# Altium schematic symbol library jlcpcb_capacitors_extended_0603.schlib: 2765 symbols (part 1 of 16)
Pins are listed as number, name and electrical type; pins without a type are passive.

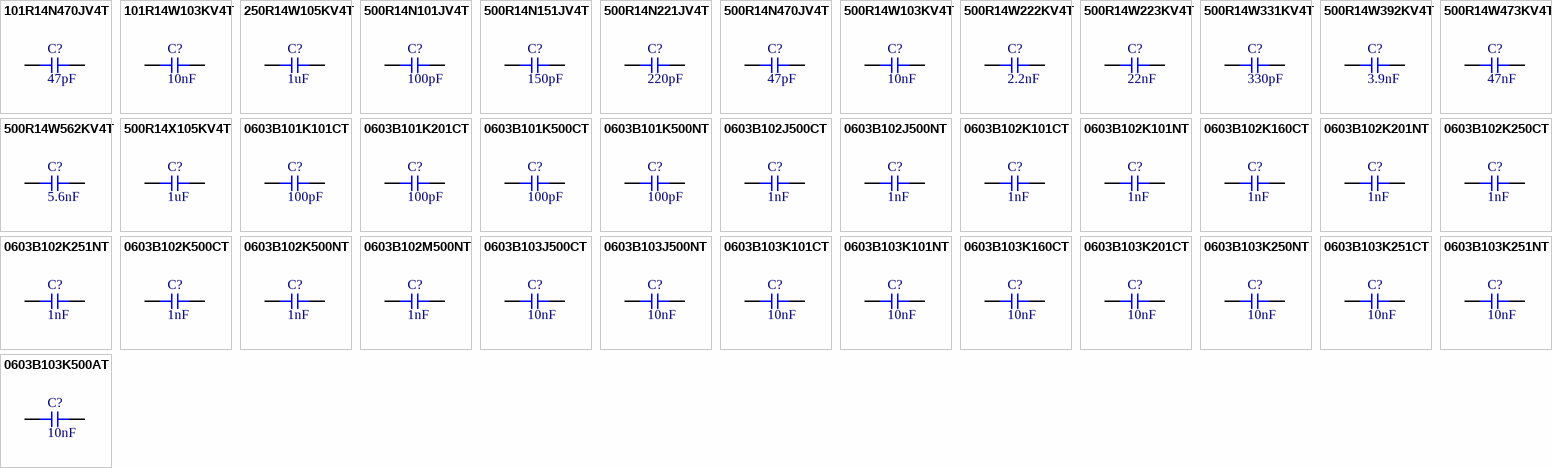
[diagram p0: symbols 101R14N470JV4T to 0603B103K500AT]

## 101R14N470JV4T
designator C?  Capacitance: 47pF  (hidden comment: *)
Capacitor, Ceramic (MLCC), 47pF, ±5%, 100V, NP0, ±5%, SMD 0603; Manufacturer: Johanson Dielectrics; Manufacturer Part Number: 101R14N470JV4T
footprint CAP-0603 (0603 (1608M) Capacitor)
pins: 1, 2

## 101R14W103KV4T
designator C?  Capacitance: 10nF  (hidden comment: *)
Capacitor, Ceramic (MLCC), 10nF, ±10%, 100V, X7R, ±10%, SMD 0603; Manufacturer: Johanson Dielectrics; Manufacturer Part Number: 101R14W103KV4T
footprint CAP-0603 (0603 (1608M) Capacitor)
pins: 1, 2

## 250R14W105KV4T
designator C?  Capacitance: 1uF  (hidden comment: *)
Capacitor, Ceramic (MLCC), 1uF, ±10%, 25V, X7R, ±10%, SMD 0603; Manufacturer: Johanson Dielectrics; Manufacturer Part Number: 250R14W105KV4T
footprint CAP-0603 (0603 (1608M) Capacitor)
pins: 1, 2

## 500R14N101JV4T
designator C?  Capacitance: 100pF  (hidden comment: *)
Capacitor, Ceramic (MLCC), 100pF, ±5%, 50V, NP0, ±5%, SMD 0603; Manufacturer: Johanson Dielectrics; Manufacturer Part Number: 500R14N101JV4T
footprint CAP-0603 (0603 (1608M) Capacitor)
pins: 1, 2

## 500R14N151JV4T
designator C?  Capacitance: 150pF  (hidden comment: *)
Capacitor, Ceramic (MLCC), 150pF, ±5%, 50V, NP0, ±5%, SMD 0603; Manufacturer: Johanson Dielectrics; Manufacturer Part Number: 500R14N151JV4T
footprint CAP-0603 (0603 (1608M) Capacitor)
pins: 1, 2

## 500R14N221JV4T
designator C?  Capacitance: 220pF  (hidden comment: *)
Capacitor, Ceramic (MLCC), 220pF, ±5%, 50V, NP0, ±5%, SMD 0603; Manufacturer: Johanson Dielectrics; Manufacturer Part Number: 500R14N221JV4T
footprint CAP-0603 (0603 (1608M) Capacitor)
pins: 1, 2

## 500R14N470JV4T
designator C?  Capacitance: 47pF  (hidden comment: *)
Capacitor, Ceramic (MLCC), 47pF, ±5%, 50V, NP0, ±5%, SMD 0603; Manufacturer: Johanson Dielectrics; Manufacturer Part Number: 500R14N470JV4T
footprint CAP-0603 (0603 (1608M) Capacitor)
pins: 1, 2

## 500R14W103KV4T
designator C?  Capacitance: 10nF  (hidden comment: *)
Capacitor, Ceramic (MLCC), 10nF, ±10%, 50V, X7R, ±10%, SMD 0603; Manufacturer: Johanson Dielectrics; Manufacturer Part Number: 500R14W103KV4T
footprint CAP-0603 (0603 (1608M) Capacitor)
pins: 1, 2

## 500R14W222KV4T
designator C?  Capacitance: 2.2nF  (hidden comment: *)
Capacitor, Ceramic (MLCC), 2.2nF, ±10%, 50V, X7R, ±10%, SMD 0603; Manufacturer: Johanson Dielectrics; Manufacturer Part Number: 500R14W222KV4T
footprint CAP-0603 (0603 (1608M) Capacitor)
pins: 1, 2

## 500R14W223KV4T
designator C?  Capacitance: 22nF  (hidden comment: *)
Capacitor, Ceramic (MLCC), 22nF, ±10%, 50V, X7R, ±10%, SMD 0603; Manufacturer: Johanson Dielectrics; Manufacturer Part Number: 500R14W223KV4T
footprint CAP-0603 (0603 (1608M) Capacitor)
pins: 1, 2

## 500R14W331KV4T
designator C?  Capacitance: 330pF  (hidden comment: *)
Capacitor, Ceramic (MLCC), 330pF, ±10%, 50V, X7R, ±10%, SMD 0603; Manufacturer: Johanson Dielectrics; Manufacturer Part Number: 500R14W331KV4T
footprint CAP-0603 (0603 (1608M) Capacitor)
pins: 1, 2

## 500R14W392KV4T
designator C?  Capacitance: 3.9nF  (hidden comment: *)
Capacitor, Ceramic (MLCC), 3.9nF, ±10%, 50V, X7R, ±10%, SMD 0603; Manufacturer: Johanson Dielectrics; Manufacturer Part Number: 500R14W392KV4T
footprint CAP-0603 (0603 (1608M) Capacitor)
pins: 1, 2

## 500R14W473KV4T
designator C?  Capacitance: 47nF  (hidden comment: *)
Capacitor, Ceramic (MLCC), 47nF, ±10%, 50V, X7R, ±10%, SMD 0603; Manufacturer: Johanson Dielectrics; Manufacturer Part Number: 500R14W473KV4T
footprint CAP-0603 (0603 (1608M) Capacitor)
pins: 1, 2

## 500R14W562KV4T
designator C?  Capacitance: 5.6nF  (hidden comment: *)
Capacitor, Ceramic (MLCC), 5.6nF, ±10%, 50V, X7R, ±10%, SMD 0603; Manufacturer: Johanson Dielectrics; Manufacturer Part Number: 500R14W562KV4T
footprint CAP-0603 (0603 (1608M) Capacitor)
pins: 1, 2

## 500R14X105KV4T
designator C?  Capacitance: 1uF  (hidden comment: *)
Capacitor, Ceramic (MLCC), 1uF, ±10%, 50V, X5R, ±10%, SMD 0603; Manufacturer: Johanson Dielectrics; Manufacturer Part Number: 500R14X105KV4T
footprint CAP-0603 (0603 (1608M) Capacitor)
pins: 1, 2

## 0603B101K101CT
designator C?  Capacitance: 100pF  (hidden comment: *)
Capacitor, Ceramic (MLCC), 100pF, ±10%, 100V, X7R, ±10%, SMD 0603; Manufacturer: Walsin Tech Corp; Manufacturer Part Number: 0603B101K101CT
footprint CAP-0603 (0603 (1608M) Capacitor)
pins: 1, 2

## 0603B101K201CT
designator C?  Capacitance: 100pF  (hidden comment: *)
Capacitor, Ceramic (MLCC), 100pF, ±10%, 200V, X7R, ±10%, SMD 0603; Manufacturer: Walsin Tech Corp; Manufacturer Part Number: 0603B101K201CT
footprint CAP-0603 (0603 (1608M) Capacitor)
pins: 1, 2

## 0603B101K500CT
designator C?  Capacitance: 100pF  (hidden comment: *)
Capacitor, Ceramic (MLCC), 100pF, ±10%, 50V, X7R, ±10%, SMD 0603; Manufacturer: Walsin Tech Corp; Manufacturer Part Number: 0603B101K500CT
footprint CAP-0603 (0603 (1608M) Capacitor)
pins: 1, 2

## 0603B101K500NT
designator C?  Capacitance: 100pF  (hidden comment: *)
Capacitor, Ceramic (MLCC), 100pF, ±10%, 50V, X7R, ±10%, SMD 0603; Manufacturer: FH(Guangdong Fenghua Advanced Tech); Manufacturer Part Number: 0603B101K500NT
footprint CAP-0603 (0603 (1608M) Capacitor)
pins: 1, 2

## 0603B102J500CT
designator C?  Capacitance: 1nF  (hidden comment: *)
Capacitor, Ceramic (MLCC), 1nF, ±5%, 50V, X7R, ±5%, SMD 0603; Manufacturer: Walsin Tech Corp; Manufacturer Part Number: 0603B102J500CT
footprint CAP-0603 (0603 (1608M) Capacitor)
pins: 1, 2

## 0603B102J500NT
designator C?  Capacitance: 1nF  (hidden comment: *)
Capacitor, Ceramic (MLCC), 1nF, ±5%, 50V, X7R, ±5%, SMD 0603; Manufacturer: FH(Guangdong Fenghua Advanced Tech); Manufacturer Part Number: 0603B102J500NT
footprint CAP-0603 (0603 (1608M) Capacitor)
pins: 1, 2

## 0603B102K101CT
designator C?  Capacitance: 1nF  (hidden comment: *)
Capacitor, Ceramic (MLCC), 1nF, ±10%, 100V, X7R, ±10%, SMD 0603; Manufacturer: Walsin Tech Corp; Manufacturer Part Number: 0603B102K101CT
footprint CAP-0603 (0603 (1608M) Capacitor)
pins: 1, 2

## 0603B102K101NT
designator C?  Capacitance: 1nF  (hidden comment: *)
Capacitor, Ceramic (MLCC), 1nF, ±10%, 100V, X7R, ±10%, SMD 0603; Manufacturer: FH(Guangdong Fenghua Advanced Tech); Manufacturer Part Number: 0603B102K101NT
footprint CAP-0603 (0603 (1608M) Capacitor)
pins: 1, 2

## 0603B102K160CT
designator C?  Capacitance: 1nF  (hidden comment: *)
Capacitor, Ceramic (MLCC), 1nF, ±10%, 16V, X7R, ±10%, SMD 0603; Manufacturer: Walsin Tech Corp; Manufacturer Part Number: 0603B102K160CT
footprint CAP-0603 (0603 (1608M) Capacitor)
pins: 1, 2

## 0603B102K201NT
designator C?  Capacitance: 1nF  (hidden comment: *)
Capacitor, Ceramic (MLCC), 1nF, ±10%, 200V, X7R, ±10%, SMD 0603; Manufacturer: FH(Guangdong Fenghua Advanced Tech); Manufacturer Part Number: 0603B102K201NT
footprint CAP-0603 (0603 (1608M) Capacitor)
pins: 1, 2

## 0603B102K250CT
designator C?  Capacitance: 1nF  (hidden comment: *)
Capacitor, Ceramic (MLCC), 1nF, ±10%, 25V, X7R, ±10%, SMD 0603; Manufacturer: Walsin Tech Corp; Manufacturer Part Number: 0603B102K250CT
footprint CAP-0603 (0603 (1608M) Capacitor)
pins: 1, 2

## 0603B102K251NT
designator C?  Capacitance: 1nF  (hidden comment: *)
Capacitor, Ceramic (MLCC), 1nF, ±10%, 250V, X7R, ±10%, SMD 0603; Manufacturer: FH(Guangdong Fenghua Advanced Tech); Manufacturer Part Number: 0603B102K251NT
footprint CAP-0603 (0603 (1608M) Capacitor)
pins: 1, 2

## 0603B102K500CT
designator C?  Capacitance: 1nF  (hidden comment: *)
Capacitor, Ceramic (MLCC), 1nF, ±10%, 50V, X7R, ±10%, SMD 0603; Manufacturer: Walsin Tech Corp; Manufacturer Part Number: 0603B102K500CT
footprint CAP-0603 (0603 (1608M) Capacitor)
pins: 1, 2

## 0603B102K500NT
designator C?  Capacitance: 1nF  (hidden comment: *)
Capacitor, Ceramic (MLCC), 1nF, ±10%, 50V, X7R, ±10%, SMD 0603; Manufacturer: FH(Guangdong Fenghua Advanced Tech); Manufacturer Part Number: 0603B102K500NT
footprint CAP-0603 (0603 (1608M) Capacitor)
pins: 1, 2

## 0603B102M500NT
designator C?  Capacitance: 1nF  (hidden comment: *)
Capacitor, Ceramic (MLCC), 1nF, ±20%, 50V, X7R, ±20%, SMD 0603; Manufacturer: FH(Guangdong Fenghua Advanced Tech); Manufacturer Part Number: 0603B102M500NT
footprint CAP-0603 (0603 (1608M) Capacitor)
pins: 1, 2

## 0603B103J500CT
designator C?  Capacitance: 10nF  (hidden comment: *)
Capacitor, Ceramic (MLCC), 10nF, ±5%, 50V, X7R, ±5%, SMD 0603; Manufacturer: Walsin Tech Corp; Manufacturer Part Number: 0603B103J500CT
footprint CAP-0603 (0603 (1608M) Capacitor)
pins: 1, 2

## 0603B103J500NT
designator C?  Capacitance: 10nF  (hidden comment: *)
Capacitor, Ceramic (MLCC), 10nF, ±5%, 50V, X7R, ±5%, SMD 0603; Manufacturer: FH(Guangdong Fenghua Advanced Tech); Manufacturer Part Number: 0603B103J500NT
footprint CAP-0603 (0603 (1608M) Capacitor)
pins: 1, 2

## 0603B103K101CT
designator C?  Capacitance: 10nF  (hidden comment: *)
Capacitor, Ceramic (MLCC), 10nF, ±10%, 100V, X7R, ±10%, SMD 0603; Manufacturer: Walsin Tech Corp; Manufacturer Part Number: 0603B103K101CT
footprint CAP-0603 (0603 (1608M) Capacitor)
pins: 1, 2

## 0603B103K101NT
designator C?  Capacitance: 10nF  (hidden comment: *)
Capacitor, Ceramic (MLCC), 10nF, ±10%, 100V, X7R, ±10%, SMD 0603; Manufacturer: FH(Guangdong Fenghua Advanced Tech); Manufacturer Part Number: 0603B103K101NT
footprint CAP-0603 (0603 (1608M) Capacitor)
pins: 1, 2

## 0603B103K160CT
designator C?  Capacitance: 10nF  (hidden comment: *)
Capacitor, Ceramic (MLCC), 10nF, ±10%, 16V, X7R, ±10%, SMD 0603; Manufacturer: Walsin Tech Corp; Manufacturer Part Number: 0603B103K160CT
footprint CAP-0603 (0603 (1608M) Capacitor)
pins: 1, 2

## 0603B103K201CT
designator C?  Capacitance: 10nF  (hidden comment: *)
Capacitor, Ceramic (MLCC), 10nF, ±10%, 200V, X7R, ±10%, SMD 0603; Manufacturer: Walsin Tech Corp; Manufacturer Part Number: 0603B103K201CT
footprint CAP-0603 (0603 (1608M) Capacitor)
pins: 1, 2

## 0603B103K250NT
designator C?  Capacitance: 10nF  (hidden comment: *)
Capacitor, Ceramic (MLCC), 10nF, ±10%, 25V, X7R, ±10%, SMD 0603; Manufacturer: FH(Guangdong Fenghua Advanced Tech); Manufacturer Part Number: 0603B103K250NT
footprint CAP-0603 (0603 (1608M) Capacitor)
pins: 1, 2

## 0603B103K251CT
designator C?  Capacitance: 10nF  (hidden comment: *)
Capacitor, Ceramic (MLCC), 10nF, ±10%, 250V, X7R, ±10%, SMD 0603; Manufacturer: Walsin Tech Corp; Manufacturer Part Number: 0603B103K251CT
footprint CAP-0603 (0603 (1608M) Capacitor)
pins: 1, 2

## 0603B103K251NT
designator C?  Capacitance: 10nF  (hidden comment: *)
Capacitor, Ceramic (MLCC), 10nF, ±10%, 250V, X7R, ±10%, SMD 0603; Manufacturer: FH(Guangdong Fenghua Advanced Tech); Manufacturer Part Number: 0603B103K251NT
footprint CAP-0603 (0603 (1608M) Capacitor)
pins: 1, 2

## 0603B103K500AT
designator C?  Capacitance: 10nF  (hidden comment: *)
Capacitor, Ceramic (MLCC), 10nF, ±10%, 50V, X7R, ±10%, SMD 0603; Manufacturer: FH(Guangdong Fenghua Advanced Tech); Manufacturer Part Number: 0603B103K500AT
footprint CAP-0603 (0603 (1608M) Capacitor)
pins: 1, 2

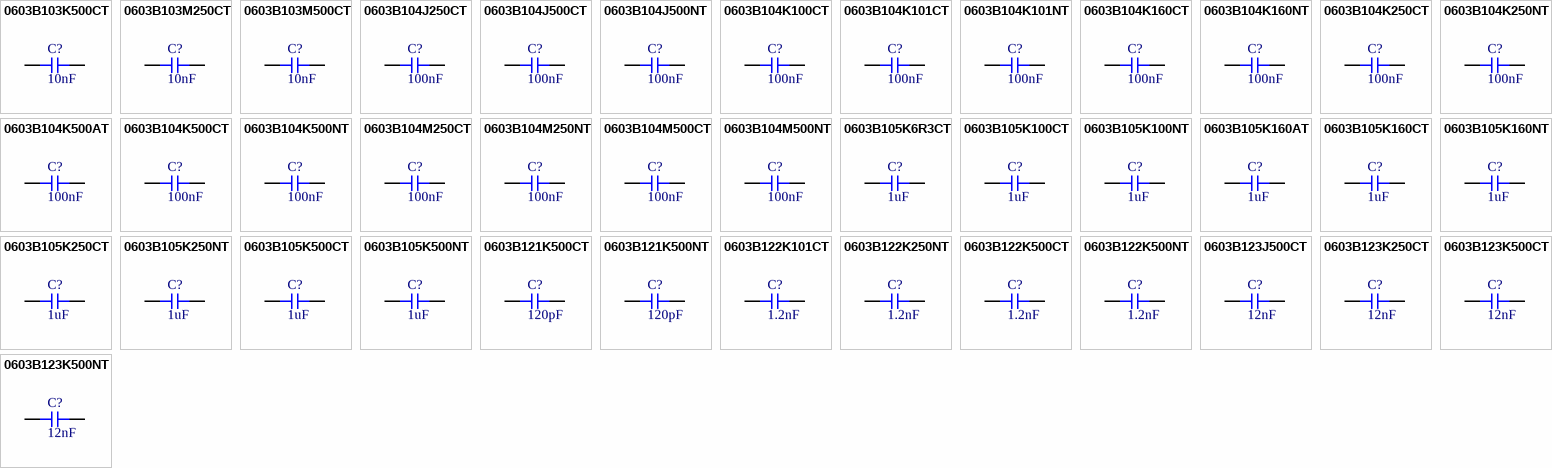
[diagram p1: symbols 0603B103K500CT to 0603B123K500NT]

## 0603B103K500CT
designator C?  Capacitance: 10nF  (hidden comment: *)
Capacitor, Ceramic (MLCC), 10nF, ±10%, 50V, X7R, ±10%, SMD 0603; Manufacturer: Walsin Tech Corp; Manufacturer Part Number: 0603B103K500CT
footprint CAP-0603 (0603 (1608M) Capacitor)
pins: 1, 2

## 0603B103M250CT
designator C?  Capacitance: 10nF  (hidden comment: *)
Capacitor, Ceramic (MLCC), 10nF, ±20%, 25V, X7R, ±20%, SMD 0603; Manufacturer: Walsin Tech Corp; Manufacturer Part Number: 0603B103M250CT
footprint CAP-0603 (0603 (1608M) Capacitor)
pins: 1, 2

## 0603B103M500CT
designator C?  Capacitance: 10nF  (hidden comment: *)
Capacitor, Ceramic (MLCC), 10nF, ±20%, 50V, X7R, ±20%, SMD 0603; Manufacturer: Walsin Tech Corp; Manufacturer Part Number: 0603B103M500CT
footprint CAP-0603 (0603 (1608M) Capacitor)
pins: 1, 2

## 0603B104J250CT
designator C?  Capacitance: 100nF  (hidden comment: *)
Capacitor, Ceramic (MLCC), 100nF, ±5%, 25V, X7R, ±5%, SMD 0603; Manufacturer: Walsin Tech Corp; Manufacturer Part Number: 0603B104J250CT
footprint CAP-0603 (0603 (1608M) Capacitor)
pins: 1, 2

## 0603B104J500CT
designator C?  Capacitance: 100nF  (hidden comment: *)
Capacitor, Ceramic (MLCC), 100nF, ±5%, 50V, X7R, ±5%, SMD 0603; Manufacturer: Walsin Tech Corp; Manufacturer Part Number: 0603B104J500CT
footprint CAP-0603 (0603 (1608M) Capacitor)
pins: 1, 2

## 0603B104J500NT
designator C?  Capacitance: 100nF  (hidden comment: *)
Capacitor, Ceramic (MLCC), 100nF, ±5%, 50V, X7R, ±5%, SMD 0603; Manufacturer: FH(Guangdong Fenghua Advanced Tech); Manufacturer Part Number: 0603B104J500NT
footprint CAP-0603 (0603 (1608M) Capacitor)
pins: 1, 2

## 0603B104K100CT
designator C?  Capacitance: 100nF  (hidden comment: *)
Capacitor, Ceramic (MLCC), 100nF, ±10%, 10V, X7R, ±10%, SMD 0603; Manufacturer: Walsin Tech Corp; Manufacturer Part Number: 0603B104K100CT
footprint CAP-0603 (0603 (1608M) Capacitor)
pins: 1, 2

## 0603B104K101CT
designator C?  Capacitance: 100nF  (hidden comment: *)
Capacitor, Ceramic (MLCC), 100nF, ±10%, 100V, X7R, ±10%, SMD 0603; Manufacturer: Walsin Tech Corp; Manufacturer Part Number: 0603B104K101CT
footprint CAP-0603 (0603 (1608M) Capacitor)
pins: 1, 2

## 0603B104K101NT
designator C?  Capacitance: 100nF  (hidden comment: *)
Capacitor, Ceramic (MLCC), 100nF, ±10%, 100V, X7R, ±10%, SMD 0603; Manufacturer: FH(Guangdong Fenghua Advanced Tech); Manufacturer Part Number: 0603B104K101NT
footprint CAP-0603 (0603 (1608M) Capacitor)
pins: 1, 2

## 0603B104K160CT
designator C?  Capacitance: 100nF  (hidden comment: *)
Capacitor, Ceramic (MLCC), 100nF, ±10%, 16V, X7R, ±10%, SMD 0603; Manufacturer: Walsin Tech Corp; Manufacturer Part Number: 0603B104K160CT
footprint CAP-0603 (0603 (1608M) Capacitor)
pins: 1, 2

## 0603B104K160NT
designator C?  Capacitance: 100nF  (hidden comment: *)
Capacitor, Ceramic (MLCC), 100nF, ±10%, 16V, X7R, ±10%, SMD 0603; Manufacturer: FH (Guangdong Fenghua Advanced Tech); Manufacturer Part Number: 0603B104K160NT
footprint CAP-0603 (0603 (1608M) Capacitor)
pins: 1, 2

## 0603B104K250CT
designator C?  Capacitance: 100nF  (hidden comment: *)
Capacitor, Ceramic (MLCC), 100nF, ±10%, 25V, X7R, ±10%, SMD 0603; Manufacturer: Walsin Tech Corp; Manufacturer Part Number: 0603B104K250CT
footprint CAP-0603 (0603 (1608M) Capacitor)
pins: 1, 2

## 0603B104K250NT
designator C?  Capacitance: 100nF  (hidden comment: *)
Capacitor, Ceramic (MLCC), 100nF, ±10%, 25V, ±10%, SMD 0603; Manufacturer: FH(Guangdong Fenghua Advanced Tech); Manufacturer Part Number: 0603B104K250NT
footprint CAP-0603 (0603 (1608M) Capacitor)
pins: 1, 2

## 0603B104K500AT
designator C?  Capacitance: 100nF  (hidden comment: *)
Capacitor, Ceramic (MLCC), 100nF, ±10%, 50V, ±10%, SMD 0603; Manufacturer: FH(Guangdong Fenghua Advanced Tech); Manufacturer Part Number: 0603B104K500AT
footprint CAP-0603 (0603 (1608M) Capacitor)
pins: 1, 2

## 0603B104K500CT
designator C?  Capacitance: 100nF  (hidden comment: *)
Capacitor, Ceramic (MLCC), 100nF, ±10%, 50V, X7R, ±10%, SMD 0603; Manufacturer: Walsin Tech Corp; Manufacturer Part Number: 0603B104K500CT
footprint CAP-0603 (0603 (1608M) Capacitor)
pins: 1, 2

## 0603B104K500NT
designator C?  Capacitance: 100nF  (hidden comment: *)
Capacitor, Ceramic (MLCC), 100nF, ±10%, 50V, X7R, ±10%, SMD 0603; Manufacturer: FH(Guangdong Fenghua Advanced Tech); Manufacturer Part Number: 0603B104K500NT
footprint CAP-0603 (0603 (1608M) Capacitor)
pins: 1, 2

## 0603B104M250CT
designator C?  Capacitance: 100nF  (hidden comment: *)
Capacitor, Ceramic (MLCC), 100nF, ±20%, 25V, X7R, ±20%, SMD 0603; Manufacturer: Walsin Tech Corp; Manufacturer Part Number: 0603B104M250CT
footprint CAP-0603 (0603 (1608M) Capacitor)
pins: 1, 2

## 0603B104M250NT
designator C?  Capacitance: 100nF  (hidden comment: *)
Capacitor, Ceramic (MLCC), 100nF, ±20%, 25V, X7R, ±20%, SMD 0603; Manufacturer: FH(Guangdong Fenghua Advanced Tech); Manufacturer Part Number: 0603B104M250NT
footprint CAP-0603 (0603 (1608M) Capacitor)
pins: 1, 2

## 0603B104M500CT
designator C?  Capacitance: 100nF  (hidden comment: *)
Capacitor, Ceramic (MLCC), 100nF, ±20%, 50V, X7R, ±20%, SMD 0603; Manufacturer: Walsin Tech Corp; Manufacturer Part Number: 0603B104M500CT
footprint CAP-0603 (0603 (1608M) Capacitor)
pins: 1, 2

## 0603B104M500NT
designator C?  Capacitance: 100nF  (hidden comment: *)
Capacitor, Ceramic (MLCC), 100nF, ±20%, 50V, X7R, ±20%, SMD 0603; Manufacturer: FH(Guangdong Fenghua Advanced Tech); Manufacturer Part Number: 0603B104M500NT
footprint CAP-0603 (0603 (1608M) Capacitor)
pins: 1, 2

## 0603B105K6R3CT
designator C?  Capacitance: 1uF  (hidden comment: *)
Capacitor, Ceramic (MLCC), 1uF, ±10%, 6.3V, X7R, ±10%, SMD 0603; Manufacturer: Walsin Tech Corp; Manufacturer Part Number: 0603B105K6R3CT
footprint CAP-0603 (0603 (1608M) Capacitor)
pins: 1, 2

## 0603B105K100CT
designator C?  Capacitance: 1uF  (hidden comment: *)
Capacitor, Ceramic (MLCC), 1uF, ±10%, 10V, X7R, ±10%, SMD 0603; Manufacturer: Walsin Tech Corp; Manufacturer Part Number: 0603B105K100CT
footprint CAP-0603 (0603 (1608M) Capacitor)
pins: 1, 2

## 0603B105K100NT
designator C?  Capacitance: 1uF  (hidden comment: *)
Capacitor, Ceramic (MLCC), 1uF, ±10%, 10V, X7R, ±10%, SMD 0603; Manufacturer: FH(Guangdong Fenghua Advanced Tech); Manufacturer Part Number: 0603B105K100NT
footprint CAP-0603 (0603 (1608M) Capacitor)
pins: 1, 2

## 0603B105K160AT
designator C?  Capacitance: 1uF  (hidden comment: *)
Capacitor, Ceramic (MLCC), 1uF, ±10%, 16V, X7R, ±10%, SMD 0603; Manufacturer: FH(Guangdong Fenghua Advanced Tech); Manufacturer Part Number: 0603B105K160AT
footprint CAP-0603 (0603 (1608M) Capacitor)
pins: 1, 2

## 0603B105K160CT
designator C?  Capacitance: 1uF  (hidden comment: *)
Capacitor, Ceramic (MLCC), 1uF, ±10%, 16V, X7R, ±10%, SMD 0603; Manufacturer: Walsin Tech Corp; Manufacturer Part Number: 0603B105K160CT
footprint CAP-0603 (0603 (1608M) Capacitor)
pins: 1, 2

## 0603B105K160NT
designator C?  Capacitance: 1uF  (hidden comment: *)
Capacitor, Ceramic (MLCC), 1uF, ±10%, 16V, X7R, ±10%, SMD 0603; Manufacturer: FH(Guangdong Fenghua Advanced Tech); Manufacturer Part Number: 0603B105K160NT
footprint CAP-0603 (0603 (1608M) Capacitor)
pins: 1, 2

## 0603B105K250CT
designator C?  Capacitance: 1uF  (hidden comment: *)
Capacitor, Ceramic (MLCC), 1uF, ±10%, 25V, X7R, ±10%, SMD 0603; Manufacturer: Walsin Tech Corp; Manufacturer Part Number: 0603B105K250CT
footprint CAP-0603 (0603 (1608M) Capacitor)
pins: 1, 2

## 0603B105K250NT
designator C?  Capacitance: 1uF  (hidden comment: *)
Capacitor, Ceramic (MLCC), 1uF, ±10%, 25V, X7R, ±10%, SMD 0603; Manufacturer: FH(Guangdong Fenghua Advanced Tech); Manufacturer Part Number: 0603B105K250NT
footprint CAP-0603 (0603 (1608M) Capacitor)
pins: 1, 2

## 0603B105K500CT
designator C?  Capacitance: 1uF  (hidden comment: *)
Capacitor, Ceramic (MLCC), 1uF, ±10%, 50V, X7R, ±10%, SMD 0603; Manufacturer: Walsin Tech Corp; Manufacturer Part Number: 0603B105K500CT
footprint CAP-0603 (0603 (1608M) Capacitor)
pins: 1, 2

## 0603B105K500NT
designator C?  Capacitance: 1uF  (hidden comment: *)
Capacitor, Ceramic (MLCC), 1uF, ±10%, 50V, X7R, ±10%, SMD 0603; Manufacturer: FH(Guangdong Fenghua Advanced Tech); Manufacturer Part Number: 0603B105K500NT
footprint CAP-0603 (0603 (1608M) Capacitor)
pins: 1, 2

## 0603B121K500CT
designator C?  Capacitance: 120pF  (hidden comment: *)
Capacitor, Ceramic (MLCC), 120pF, ±10%, 50V, X7R, ±10%, SMD 0603; Manufacturer: Walsin Tech Corp; Manufacturer Part Number: 0603B121K500CT
footprint CAP-0603 (0603 (1608M) Capacitor)
pins: 1, 2

## 0603B121K500NT
designator C?  Capacitance: 120pF  (hidden comment: *)
Capacitor, Ceramic (MLCC), 120pF, ±10%, 50V, X7R, ±10%, SMD 0603; Manufacturer: FH(Guangdong Fenghua Advanced Tech); Manufacturer Part Number: 0603B121K500NT
footprint CAP-0603 (0603 (1608M) Capacitor)
pins: 1, 2

## 0603B122K101CT
designator C?  Capacitance: 1.2nF  (hidden comment: *)
Capacitor, Ceramic (MLCC), 1.2nF, ±10%, 100V, X7R, ±10%, SMD 0603; Manufacturer: Walsin Tech Corp; Manufacturer Part Number: 0603B122K101CT
footprint CAP-0603 (0603 (1608M) Capacitor)
pins: 1, 2

## 0603B122K250NT
designator C?  Capacitance: 1.2nF  (hidden comment: *)
Capacitor, Ceramic (MLCC), 1.2nF, ±10%, 25V, X7R, ±10%, SMD 0603; Manufacturer: FH(Guangdong Fenghua Advanced Tech); Manufacturer Part Number: 0603B122K250NT
footprint CAP-0603 (0603 (1608M) Capacitor)
pins: 1, 2

## 0603B122K500CT
designator C?  Capacitance: 1.2nF  (hidden comment: *)
Capacitor, Ceramic (MLCC), 1.2nF, ±10%, 50V, X7R, ±10%, SMD 0603; Manufacturer: Walsin Tech Corp; Manufacturer Part Number: 0603B122K500CT
footprint CAP-0603 (0603 (1608M) Capacitor)
pins: 1, 2

## 0603B122K500NT
designator C?  Capacitance: 1.2nF  (hidden comment: *)
Capacitor, Ceramic (MLCC), 1.2nF, ±10%, 50V, X7R, ±10%, SMD 0603; Manufacturer: FH(Guangdong Fenghua Advanced Tech); Manufacturer Part Number: 0603B122K500NT
footprint CAP-0603 (0603 (1608M) Capacitor)
pins: 1, 2

## 0603B123J500CT
designator C?  Capacitance: 12nF  (hidden comment: *)
Capacitor, Ceramic (MLCC), 12nF, ±5%, 50V, X7R, ±5%, SMD 0603; Manufacturer: Walsin Tech Corp; Manufacturer Part Number: 0603B123J500CT
footprint CAP-0603 (0603 (1608M) Capacitor)
pins: 1, 2

## 0603B123K250CT
designator C?  Capacitance: 12nF  (hidden comment: *)
Capacitor, Ceramic (MLCC), 12nF, ±10%, 25V, X7R, ±10%, SMD 0603; Manufacturer: Walsin Tech Corp; Manufacturer Part Number: 0603B123K250CT
footprint CAP-0603 (0603 (1608M) Capacitor)
pins: 1, 2

## 0603B123K500CT
designator C?  Capacitance: 12nF  (hidden comment: *)
Capacitor, Ceramic (MLCC), 12nF, ±10%, 50V, X7R, ±10%, SMD 0603; Manufacturer: Walsin Tech Corp; Manufacturer Part Number: 0603B123K500CT
footprint CAP-0603 (0603 (1608M) Capacitor)
pins: 1, 2

## 0603B123K500NT
designator C?  Capacitance: 12nF  (hidden comment: *)
Capacitor, Ceramic (MLCC), 12nF, ±10%, 50V, X7R, ±10%, SMD 0603; Manufacturer: FH(Guangdong Fenghua Advanced Tech); Manufacturer Part Number: 0603B123K500NT
footprint CAP-0603 (0603 (1608M) Capacitor)
pins: 1, 2

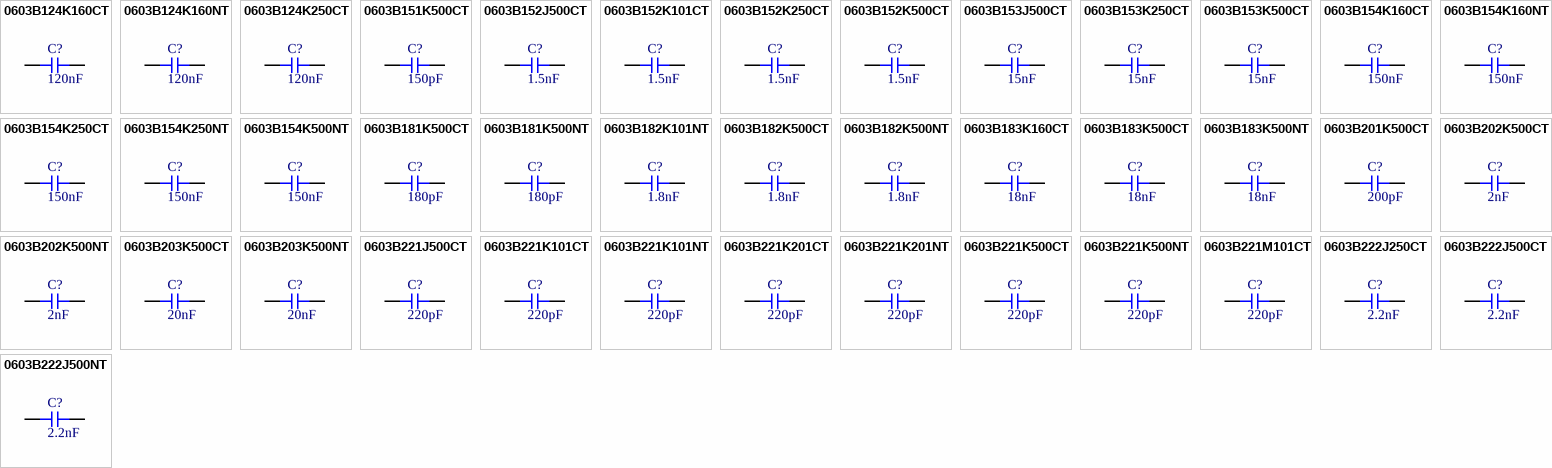
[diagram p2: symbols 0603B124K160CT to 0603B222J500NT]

## 0603B124K160CT
designator C?  Capacitance: 120nF  (hidden comment: *)
Capacitor, Ceramic (MLCC), 120nF, ±10%, 16V, X7R, ±10%, SMD 0603; Manufacturer: Walsin Tech Corp; Manufacturer Part Number: 0603B124K160CT
footprint CAP-0603 (0603 (1608M) Capacitor)
pins: 1, 2

## 0603B124K160NT
designator C?  Capacitance: 120nF  (hidden comment: *)
Capacitor, Ceramic (MLCC), 120nF, ±10%, 16V, ±10%, SMD 0603; Manufacturer: FH(Guangdong Fenghua Advanced Tech); Manufacturer Part Number: 0603B124K160NT
footprint CAP-0603 (0603 (1608M) Capacitor)
pins: 1, 2

## 0603B124K250CT
designator C?  Capacitance: 120nF  (hidden comment: *)
Capacitor, Ceramic (MLCC), 120nF, ±10%, 25V, X7R, ±10%, SMD 0603; Manufacturer: Walsin Tech Corp; Manufacturer Part Number: 0603B124K250CT
footprint CAP-0603 (0603 (1608M) Capacitor)
pins: 1, 2

## 0603B151K500CT
designator C?  Capacitance: 150pF  (hidden comment: *)
Capacitor, Ceramic (MLCC), 150pF, ±10%, 50V, X7R, ±10%, SMD 0603; Manufacturer: Walsin Tech Corp; Manufacturer Part Number: 0603B151K500CT
footprint CAP-0603 (0603 (1608M) Capacitor)
pins: 1, 2

## 0603B152J500CT
designator C?  Capacitance: 1.5nF  (hidden comment: *)
Capacitor, Ceramic (MLCC), 1.5nF, ±5%, 50V, X7R, ±5%, SMD 0603; Manufacturer: Walsin Tech Corp; Manufacturer Part Number: 0603B152J500CT
footprint CAP-0603 (0603 (1608M) Capacitor)
pins: 1, 2

## 0603B152K101CT
designator C?  Capacitance: 1.5nF  (hidden comment: *)
Capacitor, Ceramic (MLCC), 1.5nF, ±10%, 100V, X7R, ±10%, SMD 0603; Manufacturer: Walsin Tech Corp; Manufacturer Part Number: 0603B152K101CT
footprint CAP-0603 (0603 (1608M) Capacitor)
pins: 1, 2

## 0603B152K250CT
designator C?  Capacitance: 1.5nF  (hidden comment: *)
Capacitor, Ceramic (MLCC), 1.5nF, ±10%, 25V, X7R, ±10%, SMD 0603; Manufacturer: Walsin Tech Corp; Manufacturer Part Number: 0603B152K250CT
footprint CAP-0603 (0603 (1608M) Capacitor)
pins: 1, 2

## 0603B152K500CT
designator C?  Capacitance: 1.5nF  (hidden comment: *)
Capacitor, Ceramic (MLCC), 1.5nF, ±10%, 50V, X7R, ±10%, SMD 0603; Manufacturer: Walsin Tech Corp; Manufacturer Part Number: 0603B152K500CT
footprint CAP-0603 (0603 (1608M) Capacitor)
pins: 1, 2

## 0603B153J500CT
designator C?  Capacitance: 15nF  (hidden comment: *)
Capacitor, Ceramic (MLCC), 15nF, ±5%, 50V, X7R, ±5%, SMD 0603; Manufacturer: Walsin Tech Corp; Manufacturer Part Number: 0603B153J500CT
footprint CAP-0603 (0603 (1608M) Capacitor)
pins: 1, 2

## 0603B153K250CT
designator C?  Capacitance: 15nF  (hidden comment: *)
Capacitor, Ceramic (MLCC), 15nF, ±10%, 25V, X7R, ±10%, SMD 0603; Manufacturer: Walsin Tech Corp; Manufacturer Part Number: 0603B153K250CT
footprint CAP-0603 (0603 (1608M) Capacitor)
pins: 1, 2

## 0603B153K500CT
designator C?  Capacitance: 15nF  (hidden comment: *)
Capacitor, Ceramic (MLCC), 15nF, ±10%, 50V, X7R, ±10%, SMD 0603; Manufacturer: Walsin Tech Corp; Manufacturer Part Number: 0603B153K500CT
footprint CAP-0603 (0603 (1608M) Capacitor)
pins: 1, 2

## 0603B154K160CT
designator C?  Capacitance: 150nF  (hidden comment: *)
Capacitor, Ceramic (MLCC), 150nF, ±10%, 16V, X7R, ±10%, SMD 0603; Manufacturer: Walsin Tech Corp; Manufacturer Part Number: 0603B154K160CT
footprint CAP-0603 (0603 (1608M) Capacitor)
pins: 1, 2

## 0603B154K160NT
designator C?  Capacitance: 150nF  (hidden comment: *)
Capacitor, Ceramic (MLCC), 150nF, ±10%, 16V, ±10%, SMD 0603; Manufacturer: FH(Guangdong Fenghua Advanced Tech); Manufacturer Part Number: 0603B154K160NT
footprint CAP-0603 (0603 (1608M) Capacitor)
pins: 1, 2

## 0603B154K250CT
designator C?  Capacitance: 150nF  (hidden comment: *)
Capacitor, Ceramic (MLCC), 150nF, ±10%, 25V, X7R, ±10%, SMD 0603; Manufacturer: Walsin Tech Corp; Manufacturer Part Number: 0603B154K250CT
footprint CAP-0603 (0603 (1608M) Capacitor)
pins: 1, 2

## 0603B154K250NT
designator C?  Capacitance: 150nF  (hidden comment: *)
Capacitor, Ceramic (MLCC), 150nF, ±10%, 25V, X7R, ±10%, SMD 0603; Manufacturer: FH(Guangdong Fenghua Advanced Tech); Manufacturer Part Number: 0603B154K250NT
footprint CAP-0603 (0603 (1608M) Capacitor)
pins: 1, 2

## 0603B154K500NT
designator C?  Capacitance: 150nF  (hidden comment: *)
Capacitor, Ceramic (MLCC), 150nF, ±10%, 50V, X7R, ±10%, SMD 0603; Manufacturer: FH(Guangdong Fenghua Advanced Tech); Manufacturer Part Number: 0603B154K500NT
footprint CAP-0603 (0603 (1608M) Capacitor)
pins: 1, 2

## 0603B181K500CT
designator C?  Capacitance: 180pF  (hidden comment: *)
Capacitor, Ceramic (MLCC), 180pF, ±10%, 50V, X7R, ±10%, SMD 0603; Manufacturer: Walsin Tech Corp; Manufacturer Part Number: 0603B181K500CT
footprint CAP-0603 (0603 (1608M) Capacitor)
pins: 1, 2

## 0603B181K500NT
designator C?  Capacitance: 180pF  (hidden comment: *)
Capacitor, Ceramic (MLCC), 180pF, ±10%, 50V, X7R, ±10%, SMD 0603; Manufacturer: FH(Guangdong Fenghua Advanced Tech); Manufacturer Part Number: 0603B181K500NT
footprint CAP-0603 (0603 (1608M) Capacitor)
pins: 1, 2

## 0603B182K101NT
designator C?  Capacitance: 1.8nF  (hidden comment: *)
Capacitor, Ceramic (MLCC), 1.8nF, ±10%, 100V, X7R, ±10%, SMD 0603; Manufacturer: FH(Guangdong Fenghua Advanced Tech); Manufacturer Part Number: 0603B182K101NT
footprint CAP-0603 (0603 (1608M) Capacitor)
pins: 1, 2

## 0603B182K500CT
designator C?  Capacitance: 1.8nF  (hidden comment: *)
Capacitor, Ceramic (MLCC), 1.8nF, ±10%, 50V, X7R, ±10%, SMD 0603; Manufacturer: Walsin Tech Corp; Manufacturer Part Number: 0603B182K500CT
footprint CAP-0603 (0603 (1608M) Capacitor)
pins: 1, 2

## 0603B182K500NT
designator C?  Capacitance: 1.8nF  (hidden comment: *)
Capacitor, Ceramic (MLCC), 1.8nF, ±10%, 50V, X7R, ±10%, SMD 0603; Manufacturer: FH(Guangdong Fenghua Advanced Tech); Manufacturer Part Number: 0603B182K500NT
footprint CAP-0603 (0603 (1608M) Capacitor)
pins: 1, 2

## 0603B183K160CT
designator C?  Capacitance: 18nF  (hidden comment: *)
Capacitor, Ceramic (MLCC), 18nF, ±10%, 16V, X7R, ±10%, SMD 0603; Manufacturer: Walsin Tech Corp; Manufacturer Part Number: 0603B183K160CT
footprint CAP-0603 (0603 (1608M) Capacitor)
pins: 1, 2

## 0603B183K500CT
designator C?  Capacitance: 18nF  (hidden comment: *)
Capacitor, Ceramic (MLCC), 18nF, ±10%, 50V, X7R, ±10%, SMD 0603; Manufacturer: Walsin Tech Corp; Manufacturer Part Number: 0603B183K500CT
footprint CAP-0603 (0603 (1608M) Capacitor)
pins: 1, 2

## 0603B183K500NT
designator C?  Capacitance: 18nF  (hidden comment: *)
Capacitor, Ceramic (MLCC), 18nF, ±10%, 50V, X7R, ±10%, SMD 0603; Manufacturer: FH(Guangdong Fenghua Advanced Tech); Manufacturer Part Number: 0603B183K500NT
footprint CAP-0603 (0603 (1608M) Capacitor)
pins: 1, 2

## 0603B201K500CT
designator C?  Capacitance: 200pF  (hidden comment: *)
Capacitor, Ceramic (MLCC), 200pF, ±10%, 50V, X7R, ±10%, SMD 0603; Manufacturer: Walsin Tech Corp; Manufacturer Part Number: 0603B201K500CT
footprint CAP-0603 (0603 (1608M) Capacitor)
pins: 1, 2

## 0603B202K500CT
designator C?  Capacitance: 2nF  (hidden comment: *)
Capacitor, Ceramic (MLCC), 2nF, ±10%, 50V, X7R, ±10%, SMD 0603; Manufacturer: Walsin Tech Corp; Manufacturer Part Number: 0603B202K500CT
footprint CAP-0603 (0603 (1608M) Capacitor)
pins: 1, 2

## 0603B202K500NT
designator C?  Capacitance: 2nF  (hidden comment: *)
Capacitor, Ceramic (MLCC), 2nF, ±10%, 50V, X7R, ±10%, SMD 0603; Manufacturer: FH(Guangdong Fenghua Advanced Tech); Manufacturer Part Number: 0603B202K500NT
footprint CAP-0603 (0603 (1608M) Capacitor)
pins: 1, 2

## 0603B203K500CT
designator C?  Capacitance: 20nF  (hidden comment: *)
Capacitor, Ceramic (MLCC), 20nF, ±10%, 50V, X7R, ±10%, SMD 0603; Manufacturer: Walsin Tech Corp; Manufacturer Part Number: 0603B203K500CT
footprint CAP-0603 (0603 (1608M) Capacitor)
pins: 1, 2

## 0603B203K500NT
designator C?  Capacitance: 20nF  (hidden comment: *)
Capacitor, Ceramic (MLCC), 20nF, ±10%, 50V, X7R, ±10%, SMD 0603; Manufacturer: FH(Guangdong Fenghua Advanced Tech); Manufacturer Part Number: 0603B203K500NT
footprint CAP-0603 (0603 (1608M) Capacitor)
pins: 1, 2

## 0603B221J500CT
designator C?  Capacitance: 220pF  (hidden comment: *)
Capacitor, Ceramic (MLCC), 220pF, ±5%, 50V, X7R, ±5%, SMD 0603; Manufacturer: Walsin Tech Corp; Manufacturer Part Number: 0603B221J500CT
footprint CAP-0603 (0603 (1608M) Capacitor)
pins: 1, 2

## 0603B221K101CT
designator C?  Capacitance: 220pF  (hidden comment: *)
Capacitor, Ceramic (MLCC), 220pF, ±10%, 100V, X7R, ±10%, SMD 0603; Manufacturer: Walsin Tech Corp; Manufacturer Part Number: 0603B221K101CT
footprint CAP-0603 (0603 (1608M) Capacitor)
pins: 1, 2

## 0603B221K101NT
designator C?  Capacitance: 220pF  (hidden comment: *)
Capacitor, Ceramic (MLCC), 220pF, ±10%, 100V, X7R, ±10%, SMD 0603; Manufacturer: FH(Guangdong Fenghua Advanced Tech); Manufacturer Part Number: 0603B221K101NT
footprint CAP-0603 (0603 (1608M) Capacitor)
pins: 1, 2

## 0603B221K201CT
designator C?  Capacitance: 220pF  (hidden comment: *)
Capacitor, Ceramic (MLCC), 220pF, ±10%, 200V, X7R, ±10%, SMD 0603; Manufacturer: Walsin Tech Corp; Manufacturer Part Number: 0603B221K201CT
footprint CAP-0603 (0603 (1608M) Capacitor)
pins: 1, 2

## 0603B221K201NT
designator C?  Capacitance: 220pF  (hidden comment: *)
Capacitor, Ceramic (MLCC), 220pF, ±10%, 200V, X7R, ±10%, SMD 0603; Manufacturer: FH(Guangdong Fenghua Advanced Tech); Manufacturer Part Number: 0603B221K201NT
footprint CAP-0603 (0603 (1608M) Capacitor)
pins: 1, 2

## 0603B221K500CT
designator C?  Capacitance: 220pF  (hidden comment: *)
Capacitor, Ceramic (MLCC), 220pF, ±10%, 50V, X7R, ±10%, SMD 0603; Manufacturer: Walsin Tech Corp; Manufacturer Part Number: 0603B221K500CT
footprint CAP-0603 (0603 (1608M) Capacitor)
pins: 1, 2

## 0603B221K500NT
designator C?  Capacitance: 220pF  (hidden comment: *)
Capacitor, Ceramic (MLCC), 220pF, ±10%, 50V, X7R, ±10%, SMD 0603; Manufacturer: FH(Guangdong Fenghua Advanced Tech); Manufacturer Part Number: 0603B221K500NT
footprint CAP-0603 (0603 (1608M) Capacitor)
pins: 1, 2

## 0603B221M101CT
designator C?  Capacitance: 220pF  (hidden comment: *)
Capacitor, Ceramic (MLCC), 220pF, ±20%, 100V, X7R, ±20%, SMD 0603; Manufacturer: Walsin Tech Corp; Manufacturer Part Number: 0603B221M101CT
footprint CAP-0603 (0603 (1608M) Capacitor)
pins: 1, 2

## 0603B222J250CT
designator C?  Capacitance: 2.2nF  (hidden comment: *)
Capacitor, Ceramic (MLCC), 2.2nF, ±5%, 25V, X7R, ±5%, SMD 0603; Manufacturer: Walsin Tech Corp; Manufacturer Part Number: 0603B222J250CT
footprint CAP-0603 (0603 (1608M) Capacitor)
pins: 1, 2

## 0603B222J500CT
designator C?  Capacitance: 2.2nF  (hidden comment: *)
Capacitor, Ceramic (MLCC), 2.2nF, ±5%, 50V, X7R, ±5%, SMD 0603; Manufacturer: Walsin Tech Corp; Manufacturer Part Number: 0603B222J500CT
footprint CAP-0603 (0603 (1608M) Capacitor)
pins: 1, 2

## 0603B222J500NT
designator C?  Capacitance: 2.2nF  (hidden comment: *)
Capacitor, Ceramic (MLCC), 2.2nF, ±5%, 50V, X7R, ±5%, SMD 0603; Manufacturer: FH(Guangdong Fenghua Advanced Tech); Manufacturer Part Number: 0603B222J500NT
footprint CAP-0603 (0603 (1608M) Capacitor)
pins: 1, 2

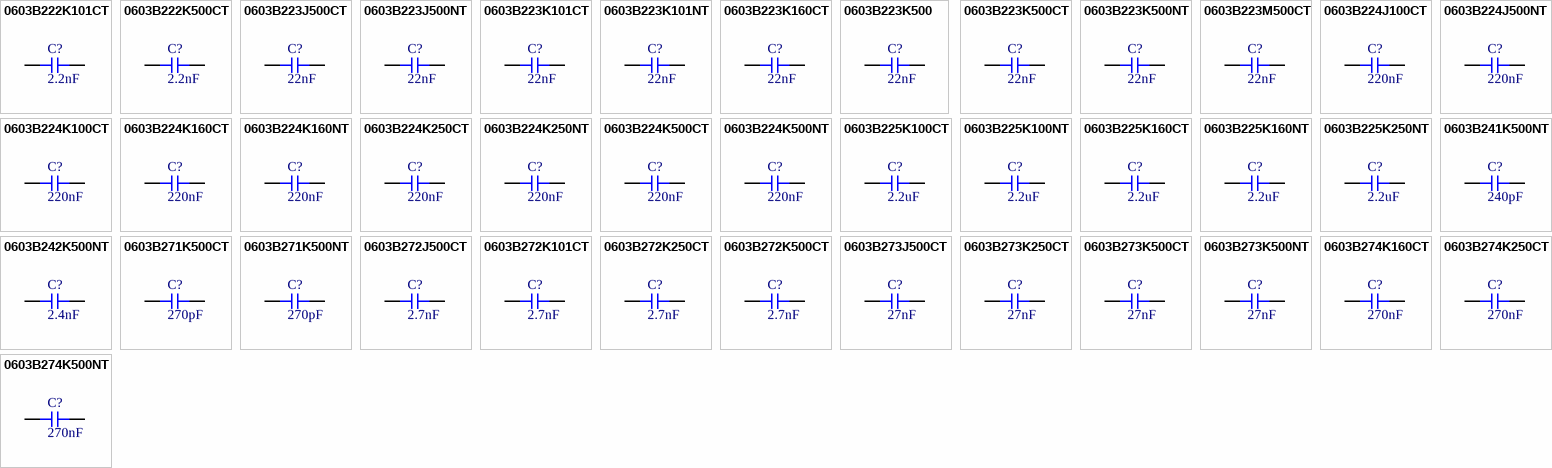
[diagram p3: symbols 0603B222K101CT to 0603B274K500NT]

## 0603B222K101CT
designator C?  Capacitance: 2.2nF  (hidden comment: *)
Capacitor, Ceramic (MLCC), 2.2nF, ±10%, 100V, X7R, ±10%, SMD 0603; Manufacturer: Walsin Tech Corp; Manufacturer Part Number: 0603B222K101CT
footprint CAP-0603 (0603 (1608M) Capacitor)
pins: 1, 2

## 0603B222K500CT
designator C?  Capacitance: 2.2nF  (hidden comment: *)
Capacitor, Ceramic (MLCC), 2.2nF, ±10%, 50V, X7R, ±10%, SMD 0603; Manufacturer: Walsin Tech Corp; Manufacturer Part Number: 0603B222K500CT
footprint CAP-0603 (0603 (1608M) Capacitor)
pins: 1, 2

## 0603B223J500CT
designator C?  Capacitance: 22nF  (hidden comment: *)
Capacitor, Ceramic (MLCC), 22nF, ±5%, 50V, X7R, ±5%, SMD 0603; Manufacturer: Walsin Tech Corp; Manufacturer Part Number: 0603B223J500CT
footprint CAP-0603 (0603 (1608M) Capacitor)
pins: 1, 2

## 0603B223J500NT
designator C?  Capacitance: 22nF  (hidden comment: *)
Capacitor, Ceramic (MLCC), 22nF, ±5%, 50V, X7R, ±5%, SMD 0603; Manufacturer: FH(Guangdong Fenghua Advanced Tech); Manufacturer Part Number: 0603B223J500NT
footprint CAP-0603 (0603 (1608M) Capacitor)
pins: 1, 2

## 0603B223K101CT
designator C?  Capacitance: 22nF  (hidden comment: *)
Capacitor, Ceramic (MLCC), 22nF, ±10%, 100V, X7R, ±10%, SMD 0603; Manufacturer: Walsin Tech Corp; Manufacturer Part Number: 0603B223K101CT
footprint CAP-0603 (0603 (1608M) Capacitor)
pins: 1, 2

## 0603B223K101NT
designator C?  Capacitance: 22nF  (hidden comment: *)
Capacitor, Ceramic (MLCC), 22nF, ±10%, 100V, X7R, ±10%, SMD 0603; Manufacturer: FH(Guangdong Fenghua Advanced Tech); Manufacturer Part Number: 0603B223K101NT
footprint CAP-0603 (0603 (1608M) Capacitor)
pins: 1, 2

## 0603B223K160CT
designator C?  Capacitance: 22nF  (hidden comment: *)
Capacitor, Ceramic (MLCC), 22nF, ±10%, 16V, X7R, ±10%, SMD 0603; Manufacturer: Walsin Tech Corp; Manufacturer Part Number: 0603B223K160CT
footprint CAP-0603 (0603 (1608M) Capacitor)
pins: 1, 2

## 0603B223K500
designator C?  Capacitance: 22nF  (hidden comment: *)
Capacitor, Ceramic (MLCC), 22nF, ±10%, 50V, X7R, ±10%, SMD 0603; Manufacturer: Walsin Tech Corp; Manufacturer Part Number: 0603B223K500
footprint CAP-0603 (0603 (1608M) Capacitor)
pins: 1, 2

## 0603B223K500CT
designator C?  Capacitance: 22nF  (hidden comment: *)
Capacitor, Ceramic (MLCC), 22nF, ±10%, 50V, X7R, ±10%, SMD 0603; Manufacturer: Walsin Tech Corp; Manufacturer Part Number: 0603B223K500CT
footprint CAP-0603 (0603 (1608M) Capacitor)
pins: 1, 2

## 0603B223K500NT
designator C?  Capacitance: 22nF  (hidden comment: *)
Capacitor, Ceramic (MLCC), 22nF, ±10%, 50V, X7R, ±10%, SMD 0603; Manufacturer: FH(Guangdong Fenghua Advanced Tech); Manufacturer Part Number: 0603B223K500NT
footprint CAP-0603 (0603 (1608M) Capacitor)
pins: 1, 2

## 0603B223M500CT
designator C?  Capacitance: 22nF  (hidden comment: *)
Capacitor, Ceramic (MLCC), 22nF, ±20%, 50V, X7R, ±20%, SMD 0603; Manufacturer: Walsin Tech Corp; Manufacturer Part Number: 0603B223M500CT
footprint CAP-0603 (0603 (1608M) Capacitor)
pins: 1, 2

## 0603B224J100CT
designator C?  Capacitance: 220nF  (hidden comment: *)
Capacitor, Ceramic (MLCC), 220nF, ±5%, 10V, X7R, ±5%, SMD 0603; Manufacturer: Walsin Tech Corp; Manufacturer Part Number: 0603B224J100CT
footprint CAP-0603 (0603 (1608M) Capacitor)
pins: 1, 2

## 0603B224J500NT
designator C?  Capacitance: 220nF  (hidden comment: *)
Capacitor, Ceramic (MLCC), 220nF, ±5%, 50V, X7R, ±5%, SMD 0603; Manufacturer: FH(Guangdong Fenghua Advanced Tech); Manufacturer Part Number: 0603B224J500NT
footprint CAP-0603 (0603 (1608M) Capacitor)
pins: 1, 2

## 0603B224K100CT
designator C?  Capacitance: 220nF  (hidden comment: *)
Capacitor, Ceramic (MLCC), 220nF, ±10%, 10V, X7R, ±10%, SMD 0603; Manufacturer: Walsin Tech Corp; Manufacturer Part Number: 0603B224K100CT
footprint CAP-0603 (0603 (1608M) Capacitor)
pins: 1, 2

## 0603B224K160CT
designator C?  Capacitance: 220nF  (hidden comment: *)
Capacitor, Ceramic (MLCC), 220nF, ±10%, 16V, X7R, ±10%, SMD 0603; Manufacturer: Walsin Tech Corp; Manufacturer Part Number: 0603B224K160CT
footprint CAP-0603 (0603 (1608M) Capacitor)
pins: 1, 2

## 0603B224K160NT
designator C?  Capacitance: 220nF  (hidden comment: *)
Capacitor, Ceramic (MLCC), 220nF, ±10%, 16V, ±10%, SMD 0603; Manufacturer: FH(Guangdong Fenghua Advanced Tech); Manufacturer Part Number: 0603B224K160NT
footprint CAP-0603 (0603 (1608M) Capacitor)
pins: 1, 2

## 0603B224K250CT
designator C?  Capacitance: 220nF  (hidden comment: *)
Capacitor, Ceramic (MLCC), 220nF, ±10%, 25V, X7R, ±10%, SMD 0603; Manufacturer: Walsin Tech Corp; Manufacturer Part Number: 0603B224K250CT
footprint CAP-0603 (0603 (1608M) Capacitor)
pins: 1, 2

## 0603B224K250NT
designator C?  Capacitance: 220nF  (hidden comment: *)
Capacitor, Ceramic (MLCC), 220nF, ±10%, 25V, X7R, ±10%, SMD 0603; Manufacturer: FH(Guangdong Fenghua Advanced Tech); Manufacturer Part Number: 0603B224K250NT
footprint CAP-0603 (0603 (1608M) Capacitor)
pins: 1, 2

## 0603B224K500CT
designator C?  Capacitance: 220nF  (hidden comment: *)
Capacitor, Ceramic (MLCC), 220nF, ±10%, 50V, X7R, ±10%, SMD 0603; Manufacturer: Walsin Tech Corp; Manufacturer Part Number: 0603B224K500CT
footprint CAP-0603 (0603 (1608M) Capacitor)
pins: 1, 2

## 0603B224K500NT
designator C?  Capacitance: 220nF  (hidden comment: *)
Capacitor, Ceramic (MLCC), 220nF, ±10%, 50V, X7R, ±10%, SMD 0603; Manufacturer: FH(Guangdong Fenghua Advanced Tech); Manufacturer Part Number: 0603B224K500NT
footprint CAP-0603 (0603 (1608M) Capacitor)
pins: 1, 2

## 0603B225K100CT
designator C?  Capacitance: 2.2uF  (hidden comment: *)
Capacitor, Ceramic (MLCC), 2.2uF, ±10%, 10V, X7R, ±10%, SMD 0603; Manufacturer: Walsin Tech Corp; Manufacturer Part Number: 0603B225K100CT
footprint CAP-0603 (0603 (1608M) Capacitor)
pins: 1, 2

## 0603B225K100NT
designator C?  Capacitance: 2.2uF  (hidden comment: *)
Capacitor, Ceramic (MLCC), 2.2uF, ±10%, 10V, X7R, ±10%, SMD 0603; Manufacturer: FH(Guangdong Fenghua Advanced Tech); Manufacturer Part Number: 0603B225K100NT
footprint CAP-0603 (0603 (1608M) Capacitor)
pins: 1, 2

## 0603B225K160CT
designator C?  Capacitance: 2.2uF  (hidden comment: *)
Capacitor, Ceramic (MLCC), 2.2uF, ±10%, 16V, X7R, ±10%, SMD 0603; Manufacturer: Walsin Tech Corp; Manufacturer Part Number: 0603B225K160CT
footprint CAP-0603 (0603 (1608M) Capacitor)
pins: 1, 2

## 0603B225K160NT
designator C?  Capacitance: 2.2uF  (hidden comment: *)
Capacitor, Ceramic (MLCC), 2.2uF, ±10%, 16V, X7R, ±10%, SMD 0603; Manufacturer: FH(Guangdong Fenghua Advanced Tech); Manufacturer Part Number: 0603B225K160NT
footprint CAP-0603 (0603 (1608M) Capacitor)
pins: 1, 2

## 0603B225K250NT
designator C?  Capacitance: 2.2uF  (hidden comment: *)
Capacitor, Ceramic (MLCC), 2.2uF, ±10%, 25V, X7R, ±10%, SMD 0603; Manufacturer: FH(Guangdong Fenghua Advanced Tech); Manufacturer Part Number: 0603B225K250NT
footprint CAP-0603 (0603 (1608M) Capacitor)
pins: 1, 2

## 0603B241K500NT
designator C?  Capacitance: 240pF  (hidden comment: *)
Capacitor, Ceramic (MLCC), 240pF, ±10%, 50V, X7R, ±10%, SMD 0603; Manufacturer: FH(Guangdong Fenghua Advanced Tech); Manufacturer Part Number: 0603B241K500NT
footprint CAP-0603 (0603 (1608M) Capacitor)
pins: 1, 2

## 0603B242K500NT
designator C?  Capacitance: 2.4nF  (hidden comment: *)
Capacitor, Ceramic (MLCC), 2.4nF, ±10%, 50V, X7R, ±10%, SMD 0603; Manufacturer: FH (Guangdong Fenghua Advanced Tech); Manufacturer Part Number: 0603B242K500NT
footprint CAP-0603 (0603 (1608M) Capacitor)
pins: 1, 2

## 0603B271K500CT
designator C?  Capacitance: 270pF  (hidden comment: *)
Capacitor, Ceramic (MLCC), 270pF, ±10%, 50V, X7R, ±10%, SMD 0603; Manufacturer: Walsin Tech Corp; Manufacturer Part Number: 0603B271K500CT
footprint CAP-0603 (0603 (1608M) Capacitor)
pins: 1, 2

## 0603B271K500NT
designator C?  Capacitance: 270pF  (hidden comment: *)
Capacitor, Ceramic (MLCC), 270pF, ±10%, 50V, X7R, ±10%, SMD 0603; Manufacturer: FH(Guangdong Fenghua Advanced Tech); Manufacturer Part Number: 0603B271K500NT
footprint CAP-0603 (0603 (1608M) Capacitor)
pins: 1, 2

## 0603B272J500CT
designator C?  Capacitance: 2.7nF  (hidden comment: *)
Capacitor, Ceramic (MLCC), 2.7nF, ±5%, 50V, X7R, ±5%, SMD 0603; Manufacturer: Walsin Tech Corp; Manufacturer Part Number: 0603B272J500CT
footprint CAP-0603 (0603 (1608M) Capacitor)
pins: 1, 2

## 0603B272K101CT
designator C?  Capacitance: 2.7nF  (hidden comment: *)
Capacitor, Ceramic (MLCC), 2.7nF, ±10%, 100V, X7R, ±10%, SMD 0603; Manufacturer: Walsin Tech Corp; Manufacturer Part Number: 0603B272K101CT
footprint CAP-0603 (0603 (1608M) Capacitor)
pins: 1, 2

## 0603B272K250CT
designator C?  Capacitance: 2.7nF  (hidden comment: *)
Capacitor, Ceramic (MLCC), 2.7nF, ±10%, 25V, X7R, ±10%, SMD 0603; Manufacturer: Walsin Tech Corp; Manufacturer Part Number: 0603B272K250CT
footprint CAP-0603 (0603 (1608M) Capacitor)
pins: 1, 2

## 0603B272K500CT
designator C?  Capacitance: 2.7nF  (hidden comment: *)
Capacitor, Ceramic (MLCC), 2.7nF, ±10%, 50V, X7R, ±10%, SMD 0603; Manufacturer: Walsin Tech Corp; Manufacturer Part Number: 0603B272K500CT
footprint CAP-0603 (0603 (1608M) Capacitor)
pins: 1, 2

## 0603B273J500CT
designator C?  Capacitance: 27nF  (hidden comment: *)
Capacitor, Ceramic (MLCC), 27nF, ±5%, 50V, X7R, ±5%, SMD 0603; Manufacturer: Walsin Tech Corp; Manufacturer Part Number: 0603B273J500CT
footprint CAP-0603 (0603 (1608M) Capacitor)
pins: 1, 2

## 0603B273K250CT
designator C?  Capacitance: 27nF  (hidden comment: *)
Capacitor, Ceramic (MLCC), 27nF, ±10%, 25V, X7R, ±10%, SMD 0603; Manufacturer: Walsin Tech Corp; Manufacturer Part Number: 0603B273K250CT
footprint CAP-0603 (0603 (1608M) Capacitor)
pins: 1, 2

## 0603B273K500CT
designator C?  Capacitance: 27nF  (hidden comment: *)
Capacitor, Ceramic (MLCC), 27nF, ±10%, 50V, X7R, ±10%, SMD 0603; Manufacturer: Walsin Tech Corp; Manufacturer Part Number: 0603B273K500CT
footprint CAP-0603 (0603 (1608M) Capacitor)
pins: 1, 2

## 0603B273K500NT
designator C?  Capacitance: 27nF  (hidden comment: *)
Capacitor, Ceramic (MLCC), 27nF, ±10%, 50V, X7R, ±10%, SMD 0603; Manufacturer: FH(Guangdong Fenghua Advanced Tech); Manufacturer Part Number: 0603B273K500NT
footprint CAP-0603 (0603 (1608M) Capacitor)
pins: 1, 2

## 0603B274K160CT
designator C?  Capacitance: 270nF  (hidden comment: *)
Capacitor, Ceramic (MLCC), 270nF, ±10%, 16V, X7R, ±10%, SMD 0603; Manufacturer: Walsin Tech Corp; Manufacturer Part Number: 0603B274K160CT
footprint CAP-0603 (0603 (1608M) Capacitor)
pins: 1, 2

## 0603B274K250CT
designator C?  Capacitance: 270nF  (hidden comment: *)
Capacitor, Ceramic (MLCC), 270nF, ±10%, 25V, X7R, ±10%, SMD 0603; Manufacturer: Walsin Tech Corp; Manufacturer Part Number: 0603B274K250CT
footprint CAP-0603 (0603 (1608M) Capacitor)
pins: 1, 2

## 0603B274K500NT
designator C?  Capacitance: 270nF  (hidden comment: *)
Capacitor, Ceramic (MLCC), 270nF, ±10%, 50V, X7R, ±10%, SMD 0603; Manufacturer: FH (Guangdong Fenghua Advanced Tech); Manufacturer Part Number: 0603B274K500NT
footprint CAP-0603 (0603 (1608M) Capacitor)
pins: 1, 2

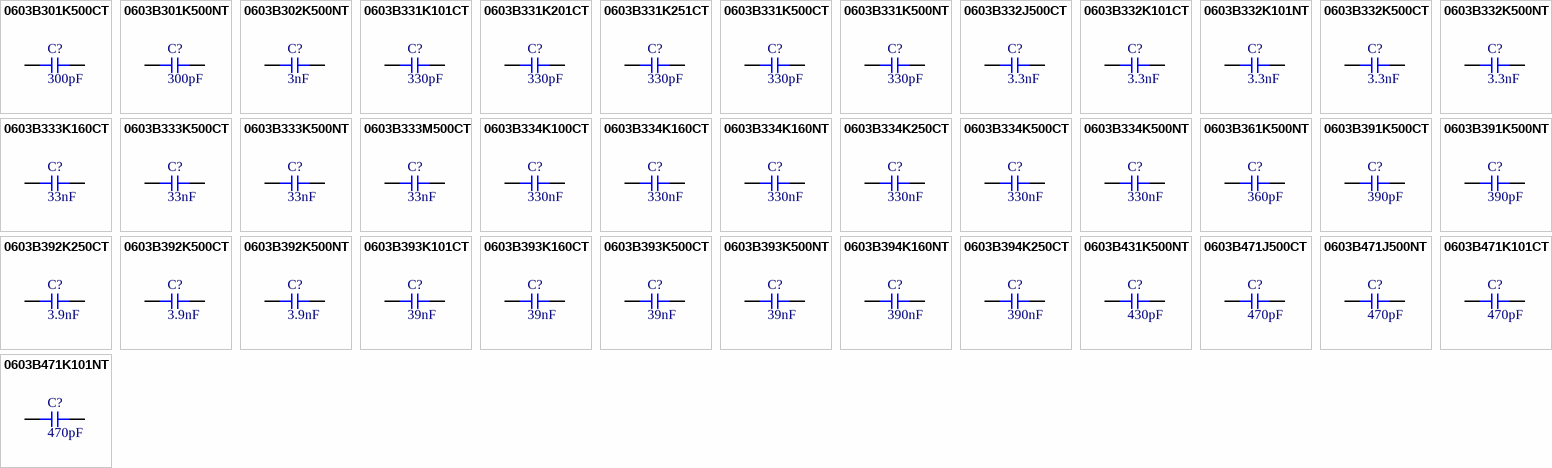
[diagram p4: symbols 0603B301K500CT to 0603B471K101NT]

## 0603B301K500CT
designator C?  Capacitance: 300pF  (hidden comment: *)
Capacitor, Ceramic (MLCC), 300pF, ±10%, 50V, X7R, ±10%, SMD 0603; Manufacturer: Walsin Tech Corp; Manufacturer Part Number: 0603B301K500CT
footprint CAP-0603 (0603 (1608M) Capacitor)
pins: 1, 2

## 0603B301K500NT
designator C?  Capacitance: 300pF  (hidden comment: *)
Capacitor, Ceramic (MLCC), 300pF, ±10%, 50V, X7R, ±10%, SMD 0603; Manufacturer: FH(Guangdong Fenghua Advanced Tech); Manufacturer Part Number: 0603B301K500NT
footprint CAP-0603 (0603 (1608M) Capacitor)
pins: 1, 2

## 0603B302K500NT
designator C?  Capacitance: 3nF  (hidden comment: *)
Capacitor, Ceramic (MLCC), 3nF, ±10%, 50V, X7R, ±10%, SMD 0603; Manufacturer: FH(Guangdong Fenghua Advanced Tech); Manufacturer Part Number: 0603B302K500NT
footprint CAP-0603 (0603 (1608M) Capacitor)
pins: 1, 2

## 0603B331K101CT
designator C?  Capacitance: 330pF  (hidden comment: *)
Capacitor, Ceramic (MLCC), 330pF, ±10%, 100V, X7R, ±10%, SMD 0603; Manufacturer: Walsin Tech Corp; Manufacturer Part Number: 0603B331K101CT
footprint CAP-0603 (0603 (1608M) Capacitor)
pins: 1, 2

## 0603B331K201CT
designator C?  Capacitance: 330pF  (hidden comment: *)
Capacitor, Ceramic (MLCC), 330pF, ±10%, 200V, X7R, ±10%, SMD 0603; Manufacturer: Walsin Tech Corp; Manufacturer Part Number: 0603B331K201CT
footprint CAP-0603 (0603 (1608M) Capacitor)
pins: 1, 2

## 0603B331K251CT
designator C?  Capacitance: 330pF  (hidden comment: *)
Capacitor, Ceramic (MLCC), 330pF, ±10%, 250V, X7R, ±10%, SMD 0603; Manufacturer: Walsin Tech Corp; Manufacturer Part Number: 0603B331K251CT
footprint CAP-0603 (0603 (1608M) Capacitor)
pins: 1, 2

## 0603B331K500CT
designator C?  Capacitance: 330pF  (hidden comment: *)
Capacitor, Ceramic (MLCC), 330pF, ±10%, 50V, X7R, ±10%, SMD 0603; Manufacturer: Walsin Tech Corp; Manufacturer Part Number: 0603B331K500CT
footprint CAP-0603 (0603 (1608M) Capacitor)
pins: 1, 2

## 0603B331K500NT
designator C?  Capacitance: 330pF  (hidden comment: *)
Capacitor, Ceramic (MLCC), 330pF, ±10%, 50V, X7R, ±10%, SMD 0603; Manufacturer: FH(Guangdong Fenghua Advanced Tech); Manufacturer Part Number: 0603B331K500NT
footprint CAP-0603 (0603 (1608M) Capacitor)
pins: 1, 2

## 0603B332J500CT
designator C?  Capacitance: 3.3nF  (hidden comment: *)
Capacitor, Ceramic (MLCC), 3.3nF, ±5%, 50V, X7R, ±5%, SMD 0603; Manufacturer: Walsin Tech Corp; Manufacturer Part Number: 0603B332J500CT
footprint CAP-0603 (0603 (1608M) Capacitor)
pins: 1, 2

## 0603B332K101CT
designator C?  Capacitance: 3.3nF  (hidden comment: *)
Capacitor, Ceramic (MLCC), 3.3nF, ±10%, 100V, X7R, ±10%, SMD 0603; Manufacturer: Walsin Tech Corp; Manufacturer Part Number: 0603B332K101CT
footprint CAP-0603 (0603 (1608M) Capacitor)
pins: 1, 2

## 0603B332K101NT
designator C?  Capacitance: 3.3nF  (hidden comment: *)
Capacitor, Ceramic (MLCC), 3.3nF, ±10%, 100V, X7R, ±10%, SMD 0603; Manufacturer: FH(Guangdong Fenghua Advanced Tech); Manufacturer Part Number: 0603B332K101NT
footprint CAP-0603 (0603 (1608M) Capacitor)
pins: 1, 2

## 0603B332K500CT
designator C?  Capacitance: 3.3nF  (hidden comment: *)
Capacitor, Ceramic (MLCC), 3.3nF, ±10%, 50V, X7R, ±10%, SMD 0603; Manufacturer: Walsin Tech Corp; Manufacturer Part Number: 0603B332K500CT
footprint CAP-0603 (0603 (1608M) Capacitor)
pins: 1, 2

## 0603B332K500NT
designator C?  Capacitance: 3.3nF  (hidden comment: *)
Capacitor, Ceramic (MLCC), 3.3nF, ±10%, 50V, X7R, ±10%, SMD 0603; Manufacturer: FH(Guangdong Fenghua Advanced Tech); Manufacturer Part Number: 0603B332K500NT
footprint CAP-0603 (0603 (1608M) Capacitor)
pins: 1, 2

## 0603B333K160CT
designator C?  Capacitance: 33nF  (hidden comment: *)
Capacitor, Ceramic (MLCC), 33nF, ±10%, 16V, X7R, ±10%, SMD 0603; Manufacturer: Walsin Tech Corp; Manufacturer Part Number: 0603B333K160CT
footprint CAP-0603 (0603 (1608M) Capacitor)
pins: 1, 2

## 0603B333K500CT
designator C?  Capacitance: 33nF  (hidden comment: *)
Capacitor, Ceramic (MLCC), 33nF, ±10%, 50V, X7R, ±10%, SMD 0603; Manufacturer: Walsin Tech Corp; Manufacturer Part Number: 0603B333K500CT
footprint CAP-0603 (0603 (1608M) Capacitor)
pins: 1, 2

## 0603B333K500NT
designator C?  Capacitance: 33nF  (hidden comment: *)
Capacitor, Ceramic (MLCC), 33nF, ±10%, 50V, X7R, ±10%, SMD 0603; Manufacturer: FH(Guangdong Fenghua Advanced Tech); Manufacturer Part Number: 0603B333K500NT
footprint CAP-0603 (0603 (1608M) Capacitor)
pins: 1, 2

## 0603B333M500CT
designator C?  Capacitance: 33nF  (hidden comment: *)
Capacitor, Ceramic (MLCC), 33nF, ±20%, 50V, X7R, ±20%, SMD 0603; Manufacturer: Walsin Tech Corp; Manufacturer Part Number: 0603B333M500CT
footprint CAP-0603 (0603 (1608M) Capacitor)
pins: 1, 2

## 0603B334K100CT
designator C?  Capacitance: 330nF  (hidden comment: *)
Capacitor, Ceramic (MLCC), 330nF, ±10%, 10V, X7R, ±10%, SMD 0603; Manufacturer: Walsin Tech Corp; Manufacturer Part Number: 0603B334K100CT
footprint CAP-0603 (0603 (1608M) Capacitor)
pins: 1, 2

## 0603B334K160CT
designator C?  Capacitance: 330nF  (hidden comment: *)
Capacitor, Ceramic (MLCC), 330nF, ±10%, 16V, X7R, ±10%, SMD 0603; Manufacturer: Walsin Tech Corp; Manufacturer Part Number: 0603B334K160CT
footprint CAP-0603 (0603 (1608M) Capacitor)
pins: 1, 2

## 0603B334K160NT
designator C?  Capacitance: 330nF  (hidden comment: *)
Capacitor, Ceramic (MLCC), 330nF, ±10%, 16V, X7R, ±10%, SMD 0603; Manufacturer: FH(Guangdong Fenghua Advanced Tech); Manufacturer Part Number: 0603B334K160NT
footprint CAP-0603 (0603 (1608M) Capacitor)
pins: 1, 2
